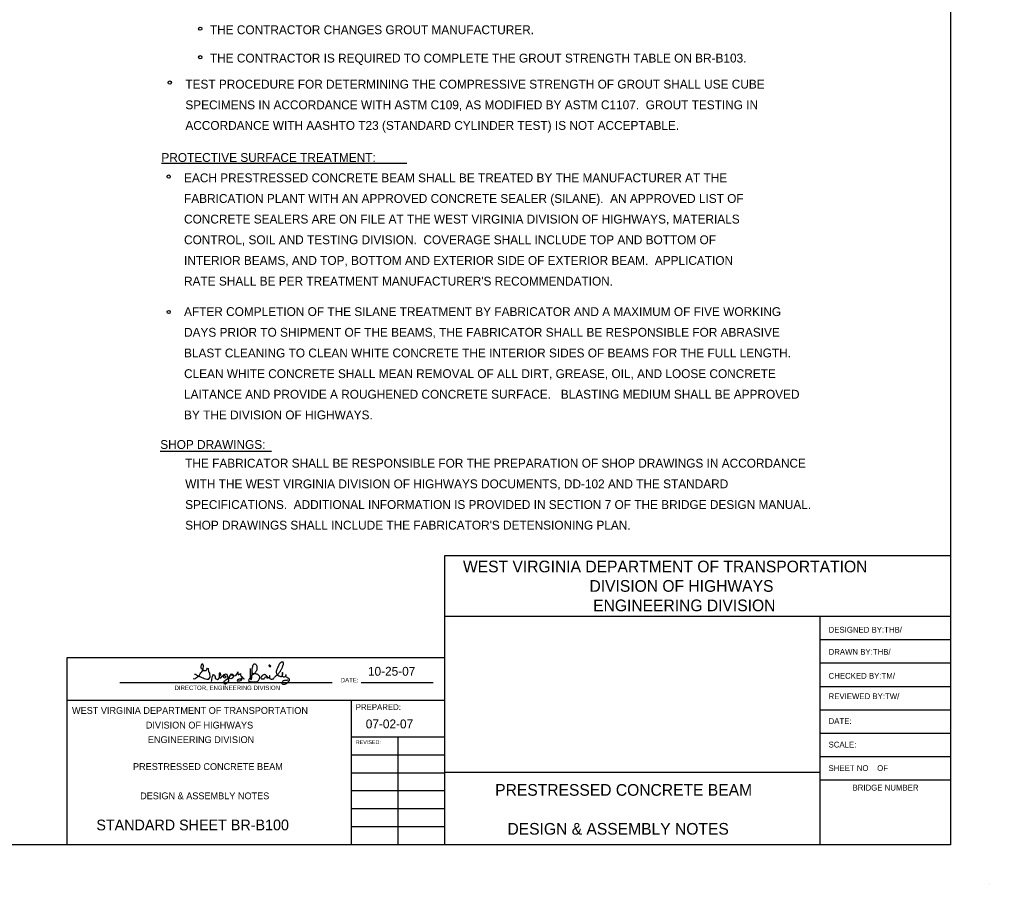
# Model space of a CAD drawing. Extents: x 762.3 to 790.4, y -1231.3 to -1213.2.
# Drawn here: x 780.09 to 790.37, y -1231.34 to -1222.18 of the extents above; entities that cross this region are included whole.
import ezdxf

# ---------------------------------------------------------------- set-up
doc = ezdxf.new("R2010")
doc.units = 0
doc.layers.add('Default', color=7, linetype='Continuous')
doc.layers.add('Level 1', color=7, linetype='Continuous')

msp = doc.modelspace()

# ---------------------------------------------------------------- linework, layer by layer
at = {"layer": 'Default'}
for p, q in [((789.954, -1213.599), (789.954, -1230.924)), ((781.593, -1223.706), (784.192, -1223.706)), ((781.581, -1226.757), (782.761, -1226.757)), ((789.954, -1227.865), (784.592, -1227.865)), ((784.592, -1227.865), (784.592, -1230.924)), ((784.592, -1227.931), (784.592, -1227.931)), ((789.954, -1227.931), (789.954, -1227.931)), ((788.568, -1228.508), (784.592, -1228.508)), ((788.568, -1228.508), (788.568, -1230.924)), ((789.954, -1228.508), (788.568, -1228.508)), ((789.954, -1228.756), (788.568, -1228.756)), ((784.592, -1228.944), (780.59, -1228.944)), ((780.59, -1228.944), (780.59, -1230.924)), ((784.592, -1228.944), (784.592, -1228.944)), ((789.954, -1229.003), (788.568, -1229.003)), ((781.152, -1229.205), (783.402, -1229.205)), ((783.71, -1229.205), (784.473, -1229.205)), ((789.954, -1229.251), (788.568, -1229.251)), ((783.602, -1229.397), (780.59, -1229.397)), ((783.602, -1229.397), (783.602, -1230.924)), ((784.592, -1229.397), (783.602, -1229.397)), ((789.954, -1229.498), (788.568, -1229.498)), ((789.954, -1229.746), (788.568, -1229.746)), ((784.592, -1229.785), (783.602, -1229.785)), ((784.097, -1229.785), (784.097, -1230.924)), ((784.592, -1229.975), (783.602, -1229.975)), ((789.954, -1229.993), (788.568, -1229.993)), ((784.592, -1230.165), (783.602, -1230.165)), ((788.568, -1230.158), (784.592, -1230.158)), ((789.954, -1230.241), (788.568, -1230.241)), ((784.592, -1230.354), (783.602, -1230.354)), ((784.592, -1230.544), (783.602, -1230.544)), ((784.592, -1230.734), (783.602, -1230.734)), ((789.954, -1230.924), (763.554, -1230.924)), ((784.592, -1230.924), (784.592, -1230.924)), ((784.592, -1230.924), (784.592, -1230.924)), ((789.954, -1230.901), (789.954, -1230.901)), ((789.954, -1230.924), (789.954, -1230.924)), ((790.367, -1231.336), (790.367, -1231.336))]:
    msp.add_line(p, q, dxfattribs=at)
for centre in [(782.005, -1222.283), (782.005, -1222.585), (781.682, -1222.853), (781.67, -1223.849), (781.67, -1225.283)]:
    msp.add_circle(centre, 0.0172, dxfattribs=at)
at = {"layer": 'Level 1'}
for points in [[(781.93, -1229.165), (781.944, -1229.167), (781.953, -1229.163), (781.965, -1229.155), (781.974, -1229.146), (781.986, -1229.139), (781.996, -1229.129), (782.002, -1229.115), (782.01, -1229.104), (782.021, -1229.095), (782.029, -1229.084), (782.035, -1229.071), (782.037, -1229.056), (782.039, -1229.042), (782.04, -1229.028), (782.032, -1229.014), (782.02, -1229.014), (782.013, -1229.024), (782.01, -1229.037), (782.01, -1229.051), (782.02, -1229.06), (782.028, -1229.072), (782.039, -1229.079), (782.054, -1229.08), (782.067, -1229.078), (782.075, -1229.067), (782.083, -1229.055), (782.09, -1229.059), (782.088, -1229.072), (782.091, -1229.085), (782.096, -1229.096), (782.101, -1229.108), (782.103, -1229.122), (782.105, -1229.136), (782.105, -1229.15), (782.097, -1229.165), (782.088, -1229.174), (782.073, -1229.174), (782.061, -1229.171), (782.047, -1229.167), (782.036, -1229.16), (782.024, -1229.157), (782.011, -1229.151), (781.999, -1229.146), (781.988, -1229.139), (781.977, -1229.135), (781.965, -1229.13), (781.955, -1229.123), (781.943, -1229.121)], [(782.534, -1229.06), (782.534, -1229.067), (782.534, -1229.073), (782.534, -1229.08), (782.534, -1229.086), (782.533, -1229.093), (782.532, -1229.099), (782.532, -1229.106), (782.532, -1229.112), (782.532, -1229.118), (782.533, -1229.125), (782.533, -1229.131), (782.533, -1229.137), (782.534, -1229.144), (782.535, -1229.15), (782.536, -1229.157), (782.536, -1229.164), (782.538, -1229.17), (782.542, -1229.175), (782.545, -1229.18), (782.547, -1229.173), (782.549, -1229.168), (782.551, -1229.161), (782.552, -1229.155), (782.552, -1229.148), (782.552, -1229.142), (782.552, -1229.136), (782.552, -1229.129), (782.553, -1229.123), (782.554, -1229.117), (782.554, -1229.11), (782.554, -1229.104), (782.554, -1229.098), (782.554, -1229.091), (782.554, -1229.085), (782.554, -1229.078), (782.554, -1229.072), (782.555, -1229.066), (782.556, -1229.059), (782.557, -1229.052), (782.559, -1229.046), (782.56, -1229.04), (782.561, -1229.033), (782.563, -1229.027), (782.566, -1229.022), (782.568, -1229.016), (782.571, -1229.01), (782.577, -1229.008), (782.584, -1229.008), (782.59, -1229.01), (782.594, -1229.015), (782.597, -1229.02), (782.6, -1229.026), (782.603, -1229.031), (782.605, -1229.038), (782.605, -1229.044), (782.605, -1229.051), (782.605, -1229.057), (782.605, -1229.063), (782.605, -1229.07), (782.604, -1229.076), (782.6, -1229.081), (782.596, -1229.085), (782.592, -1229.09), (782.589, -1229.096), (782.586, -1229.101), (782.582, -1229.106), (782.58, -1229.112), (782.575, -1229.115), (782.569, -1229.118), (782.564, -1229.122), (782.558, -1229.126), (782.554, -1229.13), (782.549, -1229.135), (782.545, -1229.14), (782.541, -1229.144), (782.537, -1229.149), (782.534, -1229.154), (782.529, -1229.16), (782.526, -1229.165), (782.523, -1229.171), (782.52, -1229.176), (782.518, -1229.182), (782.516, -1229.188), (782.519, -1229.194), (782.525, -1229.196), (782.531, -1229.197), (782.537, -1229.198), (782.544, -1229.199), (782.55, -1229.2), (782.556, -1229.2), (782.563, -1229.2), (782.57, -1229.2), (782.576, -1229.2), (782.582, -1229.2), (782.589, -1229.2), (782.595, -1229.2), (782.602, -1229.2), (782.606, -1229.195), (782.612, -1229.193), (782.617, -1229.19), (782.622, -1229.185), (782.625, -1229.179), (782.627, -1229.173), (782.631, -1229.168), (782.633, -1229.162), (782.635, -1229.156), (782.636, -1229.15), (782.636, -1229.143), (782.632, -1229.139), (782.627, -1229.135), (782.622, -1229.13), (782.618, -1229.125), (782.613, -1229.121), (782.607, -1229.118), (782.6, -1229.117), (782.594, -1229.115), (782.588, -1229.114), (782.581, -1229.114), (782.574, -1229.114), (782.567, -1229.114), (782.561, -1229.113), (782.561, -1229.113)], [(782.733, -1229.027), (782.733, -1229.033), (782.737, -1229.037), (782.744, -1229.039), (782.75, -1229.038), (782.751, -1229.032), (782.746, -1229.028), (782.742, -1229.023), (782.735, -1229.023), (782.73, -1229.026), (782.73, -1229.03)], [(782.825, -1229.122), (782.829, -1229.117), (782.832, -1229.111), (782.836, -1229.106), (782.84, -1229.102), (782.845, -1229.098), (782.849, -1229.093), (782.853, -1229.088), (782.855, -1229.082), (782.859, -1229.076), (782.863, -1229.07), (782.865, -1229.064), (782.869, -1229.058), (782.872, -1229.052), (782.875, -1229.045), (782.877, -1229.04), (782.879, -1229.034), (782.881, -1229.028), (782.883, -1229.022), (782.886, -1229.016), (782.887, -1229.009), (782.888, -1229.003), (782.887, -1228.997), (782.883, -1228.992), (782.877, -1228.99), (782.87, -1228.989), (782.865, -1228.992), (782.859, -1228.996), (782.854, -1228.998), (782.849, -1229.002), (782.846, -1229.007), (782.842, -1229.012), (782.837, -1229.017), (782.836, -1229.023), (782.834, -1229.029), (782.832, -1229.035), (782.828, -1229.04), (782.826, -1229.046), (782.822, -1229.051), (782.821, -1229.058), (782.818, -1229.063), (782.817, -1229.069), (782.814, -1229.075), (782.812, -1229.082), (782.81, -1229.088), (782.81, -1229.094), (782.81, -1229.1), (782.811, -1229.107), (782.814, -1229.113), (782.816, -1229.119), (782.819, -1229.125), (782.824, -1229.129), (782.829, -1229.131), (782.835, -1229.135), (782.841, -1229.136), (782.847, -1229.14), (782.853, -1229.142), (782.859, -1229.143), (782.866, -1229.143), (782.869, -1229.137), (782.873, -1229.132), (782.876, -1229.126), (782.878, -1229.12), (782.879, -1229.113), (782.88, -1229.106), (782.876, -1229.102), (782.873, -1229.109), (782.871, -1229.114), (782.871, -1229.121), (782.871, -1229.127), (782.871, -1229.133), (782.873, -1229.14), (782.879, -1229.143), (782.885, -1229.146), (782.891, -1229.146), (782.898, -1229.146), (782.904, -1229.144), (782.907, -1229.138), (782.911, -1229.133), (782.914, -1229.127), (782.916, -1229.121), (782.913, -1229.127), (782.91, -1229.133), (782.908, -1229.139), (782.91, -1229.144), (782.916, -1229.147), (782.922, -1229.15), (782.926, -1229.155), (782.932, -1229.157), (782.939, -1229.159), (782.943, -1229.164), (782.945, -1229.169), (782.948, -1229.175), (782.948, -1229.182), (782.946, -1229.188), (782.942, -1229.192), (782.938, -1229.197), (782.934, -1229.202), (782.93, -1229.208), (782.924, -1229.212), (782.92, -1229.216), (782.914, -1229.219), (782.908, -1229.223), (782.903, -1229.226), (782.896, -1229.227), (782.89, -1229.227), (782.883, -1229.227), (782.877, -1229.224), (782.874, -1229.219), (782.873, -1229.212), (782.873, -1229.206), (782.875, -1229.199), (782.879, -1229.194), (782.883, -1229.189), (782.888, -1229.187), (782.894, -1229.184), (782.901, -1229.183), (782.907, -1229.183), (782.913, -1229.182), (782.92, -1229.182), (782.926, -1229.181), (782.932, -1229.18), (782.936, -1229.179)], [(782.124, -1229.196), (782.128, -1229.183), (782.129, -1229.17), (782.131, -1229.157), (782.133, -1229.144), (782.138, -1229.132), (782.146, -1229.121), (782.155, -1229.129), (782.161, -1229.146), (782.164, -1229.159), (782.172, -1229.168), (782.188, -1229.175), (782.198, -1229.166), (782.206, -1229.155), (782.213, -1229.146), (782.217, -1229.133), (782.222, -1229.121), (782.22, -1229.109), (782.204, -1229.106), (782.204, -1229.119), (782.204, -1229.132), (782.205, -1229.144), (782.21, -1229.157), (782.224, -1229.158), (782.232, -1229.148), (782.237, -1229.136), (782.248, -1229.131), (782.261, -1229.131), (782.275, -1229.142), (782.271, -1229.158), (782.259, -1229.159), (782.252, -1229.148), (782.252, -1229.135), (782.256, -1229.122), (782.267, -1229.117), (782.28, -1229.114), (782.29, -1229.129), (782.294, -1229.142), (782.297, -1229.154), (782.301, -1229.166), (782.303, -1229.179), (782.303, -1229.193), (782.294, -1229.208), (782.284, -1229.216), (782.273, -1229.223), (782.26, -1229.224), (782.255, -1229.206), (782.259, -1229.194), (782.267, -1229.185), (782.276, -1229.178), (782.285, -1229.171), (782.301, -1229.161), (782.314, -1229.148), (782.318, -1229.137), (782.327, -1229.126), (782.334, -1229.116), (782.351, -1229.12), (782.354, -1229.132), (782.354, -1229.145), (782.35, -1229.157), (782.34, -1229.165), (782.328, -1229.169), (782.317, -1229.163), (782.314, -1229.151), (782.317, -1229.139), (782.325, -1229.128), (782.336, -1229.124), (782.353, -1229.131), (782.37, -1229.137), (782.384, -1229.128), (782.392, -1229.118), (782.398, -1229.106), (782.403, -1229.093), (782.403, -1229.1), (782.402, -1229.113), (782.407, -1229.124), (782.422, -1229.12), (782.43, -1229.11), (782.431, -1229.111), (782.43, -1229.124), (782.436, -1229.135), (782.446, -1229.144), (782.446, -1229.157), (782.446, -1229.169), (782.439, -1229.18), (782.43, -1229.188), (782.418, -1229.194), (782.406, -1229.197), (782.398, -1229.187), (782.406, -1229.176), (782.417, -1229.168), (782.43, -1229.166), (782.441, -1229.159), (782.458, -1229.155), (782.468, -1229.17), (782.469, -1229.169)], [(782.715, -1229.164), (782.716, -1229.158), (782.716, -1229.151), (782.716, -1229.145), (782.711, -1229.14), (782.706, -1229.136), (782.702, -1229.131), (782.697, -1229.127), (782.692, -1229.124), (782.686, -1229.121), (782.68, -1229.121), (782.673, -1229.124), (782.669, -1229.128), (782.664, -1229.132), (782.659, -1229.136), (782.655, -1229.141), (782.653, -1229.147), (782.65, -1229.152), (782.647, -1229.158), (782.651, -1229.162), (782.655, -1229.167), (782.662, -1229.169), (782.669, -1229.169), (782.675, -1229.169), (782.681, -1229.166), (782.685, -1229.161), (782.689, -1229.157), (782.693, -1229.151), (782.699, -1229.148), (782.706, -1229.148), (782.713, -1229.148), (782.719, -1229.151), (782.724, -1229.153), (782.73, -1229.157), (782.736, -1229.157), (782.738, -1229.15), (782.74, -1229.144), (782.74, -1229.137), (782.74, -1229.131), (782.738, -1229.136), (782.737, -1229.143), (782.737, -1229.149), (782.737, -1229.155), (782.737, -1229.162), (782.743, -1229.165), (782.749, -1229.168), (782.755, -1229.17), (782.762, -1229.171), (782.768, -1229.171), (782.774, -1229.169), (782.779, -1229.166), (782.783, -1229.16), (782.788, -1229.156), (782.791, -1229.15), (782.796, -1229.146), (782.801, -1229.143), (782.806, -1229.138), (782.81, -1229.133), (782.815, -1229.13), (782.821, -1229.126), (782.824, -1229.122)]]:
    msp.add_lwpolyline(points, dxfattribs=at)

# ---------------------------------------------------------------- texts
at = {"layer": 'Default'}
for s, height, p in [('THE CONTRACTOR CHANGES GROUT MANUFACTURER.', 0.09375, (782.107, -1222.341)), ('THE CONTRACTOR IS REQUIRED TO COMPLETE THE GROUT STRENGTH TABLE ON BR-B103.', 0.09375, (782.107, -1222.641)), ('TEST PROCEDURE FOR DETERMINING THE COMPRESSIVE STRENGTH OF GROUT SHALL USE CUBE ', 0.09375, (781.847, -1222.917)), ('SPECIMENS IN ACCORDANCE WITH ASTM C109, AS MODIFIED BY ASTM C1107.  GROUT TESTING IN ', 0.09375, (781.847, -1223.136)), ('ACCORDANCE WITH AASHTO T23 (STANDARD CYLINDER TEST) IS NOT ACCEPTABLE.', 0.09375, (781.847, -1223.354)), ('PROTECTIVE SURFACE TREATMENT:', 0.09375, (781.593, -1223.694)), ('EACH PRESTRESSED CONCRETE BEAM SHALL BE TREATED BY THE MANUFACTURER AT THE', 0.09375, (781.833, -1223.909)), ('FABRICATION PLANT WITH AN APPROVED CONCRETE SEALER (SILANE).  AN APPROVED LIST OF ', 0.09375, (781.833, -1224.128)), ('CONCRETE SEALERS ARE ON FILE AT THE WEST VIRGINIA DIVISION OF HIGHWAYS, MATERIALS', 0.09375, (781.833, -1224.346)), ('CONTROL, SOIL AND TESTING DIVISION.  COVERAGE SHALL INCLUDE TOP AND BOTTOM OF', 0.09375, (781.833, -1224.565)), ('INTERIOR BEAMS, AND TOP, BOTTOM AND EXTERIOR SIDE OF EXTERIOR BEAM.  APPLICATION', 0.09375, (781.833, -1224.784)), ("RATE SHALL BE PER TREATMENT MANUFACTURER'S RECOMMENDATION.", 0.09375, (781.833, -1225.003)), ('AFTER COMPLETION OF THE SILANE TREATMENT BY FABRICATOR AND A MAXIMUM OF FIVE WORKING', 0.09375, (781.833, -1225.326)), ('DAYS PRIOR TO SHIPMENT OF THE BEAMS, THE FABRICATOR SHALL BE RESPONSIBLE FOR ABRASIVE', 0.09375, (781.833, -1225.545)), ('BLAST CLEANING TO CLEAN WHITE CONCRETE THE INTERIOR SIDES OF BEAMS FOR THE FULL LENGTH.', 0.09375, (781.833, -1225.764)), ('CLEAN WHITE CONCRETE SHALL MEAN REMOVAL OF ALL DIRT, GREASE, OIL, AND LOOSE CONCRETE ', 0.09375, (781.833, -1225.983)), ('LAITANCE AND PROVIDE A ROUGHENED CONCRETE SURFACE.   BLASTING MEDIUM SHALL BE APPROVED', 0.09375, (781.833, -1226.201)), ('BY THE DIVISION OF HIGHWAYS. ', 0.09375, (781.833, -1226.42)), ('SHOP DRAWINGS:', 0.09375, (781.581, -1226.733)), ('THE FABRICATOR SHALL BE RESPONSIBLE FOR THE PREPARATION OF SHOP DRAWINGS IN ACCORDANCE', 0.09375, (781.845, -1226.931)), ('WITH THE WEST VIRGINIA DIVISION OF HIGHWAYS DOCUMENTS, DD-102 AND THE STANDARD ', 0.09375, (781.845, -1227.15)), ('SPECIFICATIONS.  ADDITIONAL INFORMATION IS PROVIDED IN SECTION 7 OF THE BRIDGE DESIGN MANUAL.', 0.09375, (781.845, -1227.369)), ("SHOP DRAWINGS SHALL INCLUDE THE FABRICATOR'S DETENSIONING PLAN.", 0.09375, (781.845, -1227.587)), ('WEST VIRGINIA DEPARTMENT OF TRANSPORTATION', 0.12375, (784.788, -1228.04)), ('DIVISION OF HIGHWAYS', 0.12375, (786.128, -1228.246)), ('ENGINEERING DIVISION', 0.12375, (786.167, -1228.452)), ('DESIGNED BY:THB/', 0.06187, (788.661, -1228.679)), ('DRAWN BY:THB/', 0.06187, (788.661, -1228.913)), ('10-25-07', 0.0938, (783.781, -1229.135)), ('CHECKED BY:TM/', 0.06187, (788.661, -1229.167)), ('DIRECTOR, ENGINEERING DIVISION', 0.04641, (781.732, -1229.286)), ('DATE:', 0.0464, (783.493, -1229.205)), ('REVIEWED BY:TW/', 0.06187, (788.661, -1229.383)), ('PREPARED:', 0.0619, (783.652, -1229.498)), ('WEST VIRGINIA DEPARTMENT OF TRANSPORTATION', 0.07219, (780.646, -1229.539)), ('DIVISION OF HIGHWAYS', 0.07219, (781.428, -1229.694)), ('07-02-07', 0.0938, (783.758, -1229.692)), ('DATE:', 0.0619, (788.661, -1229.646)), ('ENGINEERING DIVISION', 0.07219, (781.45, -1229.848)), ('REVISED:', 0.0413, (783.652, -1229.859)), ('SCALE:', 0.0619, (788.661, -1229.895)), ('PRESTRESSED CONCRETE BEAM', 0.07219, (781.292, -1230.133)), ('SHEET NO    OF', 0.06187, (788.661, -1230.144)), ('DESIGN & ASSEMBLY NOTES', 0.07219, (781.368, -1230.443)), ('PRESTRESSED CONCRETE BEAM', 0.12375, (785.129, -1230.406)), ('BRIDGE NUMBER', 0.06187, (788.915, -1230.351)), ('STANDARD SHEET BR-B100', 0.11344, (780.904, -1230.772)), ('DESIGN & ASSEMBLY NOTES', 0.12375, (785.259, -1230.818))]:
    msp.add_text(s, height=height, dxfattribs=at).set_placement(p)

doc.saveas('drawing.dxf')
